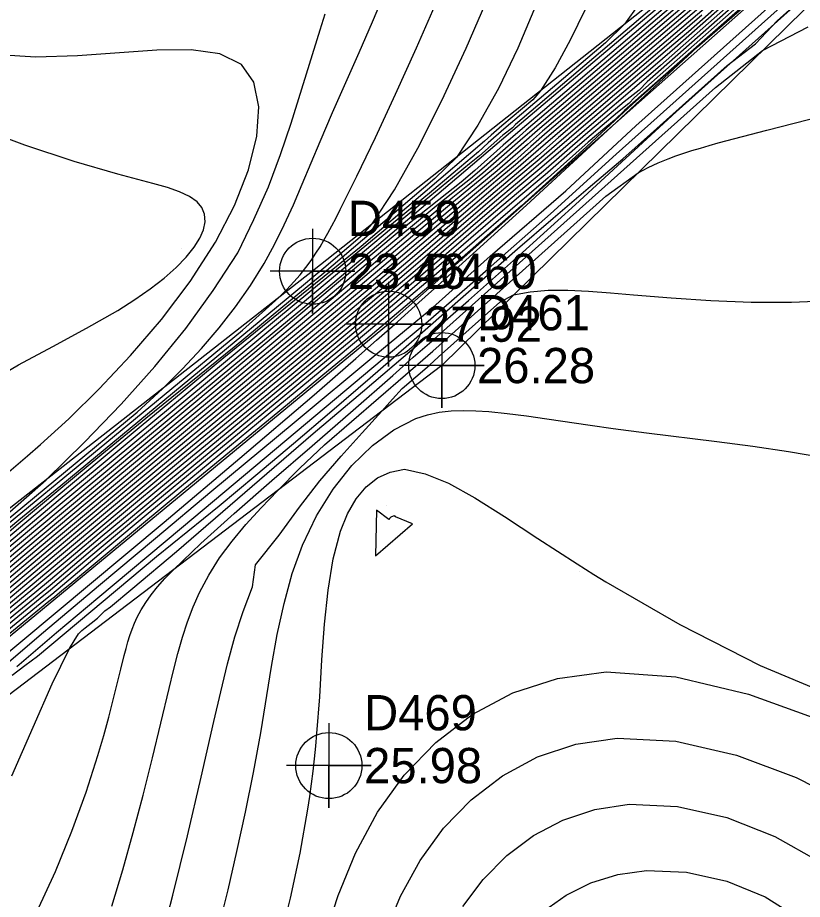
# Model space of a CAD drawing. Extents: x 2356077 to 2359823, y 225951 to 227822.
# Drawn here: x 2356677.4 to 2356733, y 226991.1 to 227053.6 of the extents above; entities that cross this region are included whole.
import ezdxf

# ---------------------------------------------------------------- set-up
doc = ezdxf.new("R2010")
doc.units = 0
for name, color, linetype in [('DTM Contours Major', 7, 'Continuous'), ('DTM Contours Minor', 7, 'Continuous'), ('Exist DTM Breakline', 7, 'Continuous'), ('Exist DTM Breakline Cogo Elevation', 7, 'Continuous'), ('Exist DTM Breakline Cogo Number', 7, 'Continuous'), ('Exist DTM Breakline Cogo Point CELL', 7, 'Continuous'), ('Exist DTM Regular Point CELL', 7, 'Continuous'), ('Exist DTM Regular Point Cogo Elevation', 7, 'Continuous'), ('Exist DTM Regular Point Cogo Number', 7, 'Continuous'), ('PH Exist DTM Point', 7, 'Continuous')]:
    doc.layers.add(name, color=color, linetype=linetype)

msp = doc.modelspace()

# ---------------------------------------------------------------- linework, layer by layer
at = {"layer": 'DTM Contours Major'}
for points in [[(2356736.154, 227061.856), (2356722.941, 227050.189), (2356721.929, 227049.303), (2356717.553, 227045.575), (2356714.539, 227042.973), (2356712.838, 227041.549), (2356711.152, 227040.115), (2356709.481, 227038.677), (2356705.347, 227035.105), (2356702.842, 227032.966), (2356701.073, 227031.472), (2356698.665, 227029.46), (2356696.111, 227027.342), (2356688.206, 227020.82), (2356685.706, 227018.748), (2356683.236, 227016.686), (2356679.71, 227013.717), (2356678.591, 227012.78), (2356668.345, 227004.388)], [(2356729.518, 227059.304), (2356713.432, 227045.6), (2356712.71, 227044.972), (2356710.444, 227042.972), (2356709.478, 227042.157), (2356708.482, 227041.368), (2356707.048, 227040.212), (2356705.641, 227039.058), (2356704.252, 227037.903), (2356701.485, 227035.576), (2356697.397, 227032.135), (2356693.102, 227028.545), (2356682.449, 227019.674), (2356677.954, 227015.918), (2356673.699, 227012.35)], [(2356676.977, 226999.821), (2356678.47, 227003.273), (2356679.827, 227006.346), (2356681.066, 227008.837), (2356681.384, 227009.387), (2356681.697, 227009.884), (2356681.937, 227010.125), (2356682.162, 227010.311), (2356682.601, 227010.639), (2356683.037, 227011.004), (2356683.553, 227011.518), (2356683.972, 227011.787), (2356685.554, 227013.109), (2356688.63, 227015.729), (2356698.316, 227024.09), (2356701.825, 227027.055), (2356705.504, 227030.182), (2356709.348, 227033.532), (2356713.169, 227036.936), (2356716.924, 227040.341), (2356724.062, 227046.907), (2356733.497, 227055.356)], [(2356717.626, 227054.212), (2356716.538, 227051.977), (2356715.472, 227050.028), (2356714.437, 227048.394), (2356713.89, 227047.758), (2356711.712, 227045.903), (2356710.944, 227045.236), (2356710.482, 227044.831), (2356701.737, 227037.351), (2356700.104, 227036.026), (2356697.5, 227033.93), (2356694.726, 227031.676), (2356692.002, 227029.444), (2356689.112, 227027.063), (2356686.137, 227024.598), (2356683.16, 227022.118), (2356680.26, 227019.691), (2356676.405, 227016.442)], [(2356725.678, 227054.264), (2356715.221, 227045.356), (2356713.951, 227044.244), (2356712.67, 227043.137), (2356711.288, 227041.981), (2356709.946, 227040.849), (2356702.897, 227034.856), (2356700.549, 227032.877), (2356698.699, 227031.332), (2356694.781, 227028.083), (2356688.67, 227023.032), (2356685.125, 227020.088), (2356681.648, 227017.188), (2356676.515, 227012.882)], [(2356675.811, 227017.665), (2356679.39, 227020.795), (2356682.125, 227023.486), (2356684.706, 227026.166), (2356687.107, 227028.844), (2356689.296, 227031.527), (2356691.246, 227034.222), (2356692.986, 227036.901), (2356694.13, 227039.264), (2356695.151, 227041.584), (2356696.023, 227043.871), (2356696.777, 227046.099), (2356698.069, 227050.273), (2356698.828, 227052.705), (2356699.18, 227053.861)], [(2356695.921, 226987.929), (2356696.722, 226991.141), (2356697.408, 226994.325), (2356697.96, 226997.437), (2356698.095, 226998.342), (2356698.218, 226999.239), (2356698.329, 227000.131), (2356698.429, 227001.021), (2356698.518, 227001.911), (2356698.598, 227002.805), (2356698.789, 227005.424), (2356698.953, 227008.033), (2356699.136, 227010.57), (2356699.385, 227012.977), (2356699.747, 227015.195), (2356700.267, 227017.165), (2356700.765, 227018.401), (2356701.369, 227019.457), (2356702.075, 227020.311), (2356702.882, 227020.945), (2356703.788, 227021.337), (2356704.813, 227021.559), (2356706.258, 227021.225), (2356707.914, 227020.558), (2356709.781, 227019.531), (2356711.883, 227018.208), (2356714.244, 227016.653), (2356717.036, 227014.836), (2356718.217, 227014.092), (2356719.083, 227013.558), (2356724.321, 227010.533), (2356730.024, 227007.639), (2356735.824, 227005.205)]]:
    msp.add_lwpolyline(points, dxfattribs=at)
at = {"layer": 'DTM Contours Minor'}
for points in [[(2356735.682, 227062.082), (2356724.925, 227052.584), (2356723.457, 227051.312), (2356715.932, 227044.9), (2356714.351, 227043.522), (2356712.766, 227042.187), (2356711.211, 227040.863), (2356705.741, 227036.16), (2356703.843, 227034.54), (2356701.871, 227032.871), (2356700.837, 227032.003), (2356698.663, 227030.189), (2356696.367, 227028.287), (2356689.217, 227022.388), (2356685.422, 227019.244), (2356682.568, 227016.861), (2356678.401, 227013.357), (2356676.583, 227011.851)], [(2356736.273, 227061.639), (2356722.003, 227049.038), (2356721.441, 227048.428), (2356720.364, 227047.616), (2356717.629, 227045.287), (2356714.647, 227042.698), (2356712.876, 227041.213), (2356711.116, 227039.713), (2356707.614, 227036.689), (2356705.116, 227034.535), (2356702.829, 227032.584), (2356701.221, 227031.226), (2356698.685, 227029.107), (2356695.992, 227026.873), (2356687.687, 227020.018), (2356685.085, 227017.858), (2356682.858, 227015.994), (2356679.678, 227013.312), (2356668.259, 227003.96)], [(2356736.926, 227061.558), (2356723.299, 227049.526), (2356720.971, 227047.456), (2356718.773, 227045.416), (2356717.724, 227044.449), (2356715.337, 227042.269), (2356713.064, 227040.221), (2356710.863, 227038.269), (2356708.697, 227036.376), (2356706.523, 227034.506), (2356703.937, 227032.314), (2356702.061, 227030.743), (2356699.019, 227028.219), (2356695.816, 227025.579), (2356689.234, 227020.164), (2356686.007, 227017.496), (2356682.305, 227014.404), (2356681.08, 227013.377), (2356680.515, 227012.926), (2356679.999, 227012.491), (2356679.594, 227012.17), (2356669.406, 227003.826)], [(2356735.905, 227061.957), (2356723.976, 227051.424), (2356722.736, 227050.344), (2356717.494, 227045.878), (2356714.442, 227043.256), (2356712.803, 227041.87), (2356711.186, 227040.487), (2356705.555, 227035.633), (2356703.772, 227034.11), (2356701.919, 227032.542), (2356700.949, 227031.726), (2356698.66, 227029.817), (2356696.237, 227027.81), (2356688.713, 227021.605), (2356686.307, 227019.614), (2356683.607, 227017.364), (2356681.022, 227015.196), (2356678.466, 227013.039), (2356672.629, 227008.254)], [(2356736.24, 227061.288), (2356721.104, 227047.923), (2356720.696, 227047.495), (2356719.891, 227046.86), (2356717.72, 227045.01), (2356716.867, 227044.266), (2356714.772, 227042.427), (2356712.915, 227040.863), (2356711.068, 227039.285), (2356705.506, 227034.491), (2356703.508, 227032.786), (2356701.412, 227031.016), (2356698.739, 227028.785), (2356695.902, 227026.435), (2356690.045, 227021.606), (2356687.181, 227019.238), (2356684.463, 227016.978), (2356681.553, 227014.532), (2356679.702, 227012.967), (2356678.971, 227012.376), (2356667.614, 227003.074)], [(2356730.285, 227060.31), (2356712.992, 227045.579), (2356711.799, 227044.532), (2356709.781, 227042.751), (2356708.827, 227041.918), (2356707.245, 227040.67), (2356705.753, 227039.482), (2356704.292, 227038.293), (2356702.85, 227037.1), (2356699.98, 227034.693), (2356694.914, 227030.44), (2356689.864, 227026.221), (2356680.205, 227018.166), (2356675.141, 227013.92)], [(2356676.984, 227006.958), (2356677.888, 227007.645), (2356678.783, 227008.309), (2356687.231, 227015.376), (2356691.657, 227018.968), (2356694.263, 227021.127), (2356696.933, 227023.376), (2356699.645, 227025.691), (2356702.375, 227028.047), (2356705.1, 227030.419), (2356712.823, 227037.185), (2356715.339, 227039.37), (2356717.825, 227041.499), (2356720.279, 227043.562), (2356722.246, 227045.313), (2356727.684, 227050.179), (2356729.692, 227051.724), (2356731.224, 227053.35), (2356739.12, 227060.427)], [(2356675.568, 227006.894), (2356679.216, 227009.997), (2356683.118, 227013.29), (2356687.14, 227016.666), (2356691.147, 227020.017), (2356696.974, 227024.874), (2356702.772, 227029.686), (2356704.795, 227031.359), (2356706.814, 227033.036), (2356710.868, 227036.664), (2356716.24, 227041.299), (2356721.201, 227045.913), (2356736.298, 227059.426)], [(2356677.311, 227007.563), (2356680.135, 227009.965), (2356683.054, 227012.427), (2356688.992, 227017.403), (2356694.254, 227021.813), (2356701.312, 227027.739), (2356703.819, 227029.837), (2356706.473, 227032.049), (2356710.545, 227035.605), (2356715.159, 227039.677), (2356719.797, 227043.888), (2356736.828, 227059.136)], [(2356733.513, 227058.557), (2356720.407, 227046.985), (2356719.695, 227046.303), (2356719.005, 227045.752), (2356717.832, 227044.752), (2356714.975, 227042.232), (2356707.064, 227035.423), (2356704.506, 227033.238), (2356702.256, 227031.338), (2356698.835, 227028.485), (2356695.832, 227026.002), (2356689.65, 227020.905), (2356686.631, 227018.407), (2356683.766, 227016.018), (2356681.313, 227013.951), (2356679.794, 227012.679), (2356679.229, 227012.229), (2356667.425, 227002.561)], [(2356728.74, 227058.287), (2356713.844, 227045.598), (2356712.999, 227044.862), (2356711.312, 227043.373), (2356710.362, 227042.55), (2356709.284, 227041.683), (2356708.231, 227040.826), (2356706.877, 227039.712), (2356705.542, 227038.6), (2356702.885, 227036.366), (2356700.186, 227034.089), (2356697.282, 227031.654), (2356692.638, 227027.786), (2356684.489, 227021.011), (2356680.122, 227017.369), (2356675.027, 227013.099)], [(2356727.967, 227057.275), (2356714.232, 227045.575), (2356713.27, 227044.737), (2356711.375, 227043.065), (2356709.108, 227041.2), (2356707.998, 227040.28), (2356706.715, 227039.209), (2356704.173, 227037.069), (2356700.28, 227033.784), (2356697.16, 227031.174), (2356686.297, 227022.152), (2356680.077, 227016.967), (2356674.971, 227012.688)], [(2356727.198, 227056.266), (2356714.593, 227045.528), (2356713.521, 227044.594), (2356712.483, 227043.678), (2356711.363, 227042.719), (2356710.137, 227041.706), (2356708.944, 227040.714), (2356706.557, 227038.707), (2356701.65, 227034.557), (2356698.729, 227032.106), (2356695.289, 227029.244), (2356687.877, 227023.102), (2356681.969, 227018.184), (2356678.125, 227014.969), (2356674.917, 227012.277)], [(2356724.255, 227055.88), (2356712.666, 227046.008), (2356712.464, 227045.772), (2356711.776, 227045.241), (2356710.111, 227043.772), (2356709.42, 227043.211), (2356707.799, 227041.884), (2356706.202, 227040.563), (2356704.623, 227039.247), (2356697.844, 227033.564), (2356693.337, 227029.811), (2356682.897, 227021.135), (2356680.255, 227018.932), (2356676.469, 227015.76)], [(2356724.672, 227055.915), (2356721.357, 227053.096), (2356712.788, 227045.836), (2356702.817, 227037.352), (2356699.855, 227034.853), (2356697.594, 227032.962), (2356692.707, 227028.906), (2356685.323, 227022.786), (2356680.24, 227018.556), (2356676.49, 227015.417)], [(2356673.001, 227005.49), (2356682.483, 227013.387), (2356687.76, 227017.801), (2356693.129, 227022.333), (2356698.392, 227026.838), (2356699.877, 227028.125), (2356701.35, 227029.409), (2356702.823, 227030.703), (2356704.311, 227032.019), (2356705.827, 227033.368), (2356707.383, 227034.763), (2356713.451, 227040.276), (2356719.796, 227046.138), (2356725.582, 227051.514), (2356729.92, 227055.291)], [(2356674.641, 227015.625), (2356677.469, 227017.964), (2356680.429, 227020.402), (2356697.65, 227034.638), (2356698.384, 227035.238), (2356699.088, 227035.834), (2356701.822, 227038.173), (2356702.521, 227038.95), (2356704.089, 227041.365), (2356705.747, 227044.317), (2356707.456, 227047.703), (2356709.179, 227051.419), (2356710.876, 227055.366)], [(2356675.672, 227017.189), (2356685.846, 227025.6), (2356687.644, 227027.259), (2356689.067, 227028.682), (2356690.408, 227030.12), (2356691.662, 227031.58), (2356692.825, 227033.067), (2356693.891, 227034.586), (2356694.855, 227036.142), (2356695.596, 227037.5), (2356696.28, 227038.89), (2356696.924, 227040.314), (2356697.549, 227041.771), (2356698.816, 227044.793), (2356699.708, 227046.854), (2356701.593, 227051.117), (2356702.54, 227053.293), (2356703.458, 227055.482)], [(2356726.435, 227055.263), (2356714.923, 227045.456), (2356713.749, 227044.431), (2356712.619, 227043.433), (2356710.038, 227041.279), (2356707.561, 227039.188), (2356702.9, 227035.234), (2356700.459, 227033.177), (2356698.714, 227031.718), (2356695.037, 227028.665), (2356687.382, 227022.328), (2356683.653, 227019.226), (2356679.982, 227016.159), (2356676.51, 227013.246)], [(2356714.166, 227054.564), (2356712.839, 227051.42), (2356711.456, 227048.548), (2356710.007, 227045.962), (2356708.478, 227043.671), (2356706.948, 227042.183), (2356698.951, 227035.342), (2356698.173, 227034.7), (2356696.183, 227033.068), (2356692.721, 227030.206), (2356686.461, 227025.154), (2356683.339, 227022.597), (2356680.295, 227020.076), (2356677.422, 227017.669), (2356674.412, 227015.121)], [(2356726.839, 227054.918), (2356724.928, 227053.272), (2356715.486, 227045.228), (2356714.123, 227044.032), (2356712.698, 227042.822), (2356711.26, 227041.61), (2356708.484, 227039.246), (2356705.03, 227036.294), (2356702.891, 227034.476), (2356700.64, 227032.581), (2356698.684, 227030.948), (2356694.522, 227027.5), (2356688.082, 227022.181), (2356684.74, 227019.404), (2356681.488, 227016.689), (2356676.522, 227012.517)], [(2356676.662, 227017.648), (2356693.314, 227031.415), (2356695.898, 227033.724), (2356696.46, 227034.296), (2356696.959, 227034.835), (2356697.405, 227035.351), (2356697.808, 227035.855), (2356698.179, 227036.358), (2356698.526, 227036.873), (2356698.812, 227037.327), (2356699.092, 227037.801), (2356699.372, 227038.299), (2356699.656, 227038.825), (2356699.947, 227039.383), (2356700.251, 227039.977), (2356701.422, 227042.333), (2356702.743, 227045.085), (2356704.166, 227048.148), (2356705.646, 227051.438), (2356707.136, 227054.87)], [(2356721.411, 227054.531), (2356720.395, 227053.116), (2356719.046, 227051.797), (2356711.847, 227045.664), (2356710.742, 227044.693), (2356710.037, 227044.076), (2356708.253, 227042.55), (2356706.57, 227041.127), (2356704.959, 227039.814), (2356703.328, 227038.473), (2356698.101, 227034.139), (2356685.857, 227023.973), (2356683.026, 227021.615), (2356680.26, 227019.305), (2356676.441, 227016.099)], [(2356725.878, 227053.748), (2356724.188, 227052.288), (2356715.721, 227045.075), (2356714.263, 227043.79), (2356712.73, 227042.505), (2356711.234, 227041.237), (2356708.331, 227038.751), (2356704.917, 227035.826), (2356702.882, 227034.096), (2356700.735, 227032.289), (2356698.672, 227030.567), (2356696.501, 227028.766), (2356687.493, 227021.328), (2356684.358, 227018.722), (2356681.33, 227016.19), (2356678.342, 227013.679), (2356676.543, 227012.176)], [(2356678.747, 226990.168), (2356680.063, 226993.02), (2356681.23, 226995.881), (2356682.237, 226998.656), (2356683.073, 227001.249), (2356683.486, 227002.663), (2356683.846, 227003.982), (2356684.161, 227005.206), (2356684.695, 227007.381), (2356684.934, 227008.334), (2356685.066, 227008.837), (2356685.201, 227009.316), (2356685.342, 227009.774), (2356685.495, 227010.214), (2356685.663, 227010.641), (2356685.851, 227011.057), (2356686.129, 227011.58), (2356686.456, 227012.105), (2356686.841, 227012.642), (2356687.294, 227013.204), (2356687.824, 227013.802), (2356688.44, 227014.447), (2356690.354, 227016.291), (2356692.719, 227018.422), (2356695.398, 227020.76), (2356698.256, 227023.224), (2356701.157, 227025.734), (2356703.965, 227028.208), (2356705.427, 227029.502), (2356706.907, 227030.779), (2356726.852, 227048.637), (2356730.179, 227051.251), (2356733.421, 227052.932)], [(2356676.434, 227021.086), (2356678.075, 227022.494), (2356679.009, 227023.31), (2356681.001, 227025.132), (2356683.163, 227027.248), (2356685.39, 227029.609), (2356687.576, 227032.164), (2356689.617, 227034.863), (2356691.407, 227037.657), (2356692.747, 227040.257), (2356693.738, 227042.793), (2356694.331, 227045.164), (2356694.478, 227047.267), (2356694.131, 227049.002), (2356693.242, 227050.266), (2356691.722, 227051.016), (2356689.682, 227051.301), (2356687.241, 227051.27), (2356681.618, 227050.863), (2356678.67, 227050.787), (2356676.012, 227050.943)], [(2356684.048, 226990.578), (2356684.837, 226993.142), (2356685.579, 226995.785), (2356686.277, 226998.45), (2356686.931, 227001.079), (2356688.119, 227006.001), (2356688.431, 227007.272), (2356688.744, 227008.481), (2356689.07, 227009.634), (2356689.424, 227010.735), (2356689.817, 227011.79), (2356690.264, 227012.804), (2356690.928, 227014.052), (2356691.699, 227015.26), (2356692.574, 227016.446), (2356693.553, 227017.629), (2356694.634, 227018.827), (2356695.814, 227020.058), (2356697.392, 227021.631), (2356699.121, 227023.274), (2356704.882, 227028.247), (2356706.805, 227029.917), (2356719.078, 227040.909), (2356721.359, 227042.582), (2356721.718, 227042.774), (2356722.073, 227042.953), (2356722.426, 227043.12), (2356722.777, 227043.278), (2356723.13, 227043.427), (2356723.485, 227043.568), (2356724.036, 227043.773), (2356724.6, 227043.967), (2356725.18, 227044.153), (2356725.779, 227044.333), (2356726.401, 227044.512), (2356727.049, 227044.691), (2356730.487, 227045.598), (2356734.358, 227046.593)], [(2356675.052, 227027.571), (2356677.442, 227028.952), (2356679.88, 227030.27), (2356682.259, 227031.549), (2356684.469, 227032.817), (2356685.676, 227033.583), (2356686.775, 227034.349), (2356687.755, 227035.11), (2356688.608, 227035.86), (2356689.326, 227036.594), (2356689.899, 227037.307), (2356690.291, 227037.94), (2356690.547, 227038.544), (2356690.662, 227039.112), (2356690.629, 227039.637), (2356690.442, 227040.112), (2356690.095, 227040.53), (2356689.562, 227040.902), (2356688.858, 227041.226), (2356687.991, 227041.524), (2356686.969, 227041.817), (2356684.489, 227042.475), (2356681.386, 227043.377), (2356677.882, 227044.532), (2356674.142, 227045.941)], [(2356687.306, 226987.23), (2356688.387, 226991.347), (2356689.417, 226995.559), (2356690.389, 226999.714), (2356691.292, 227003.661), (2356691.777, 227005.763), (2356692.266, 227007.759), (2356692.785, 227009.658), (2356693.363, 227011.471), (2356694.027, 227013.206), (2356694.243, 227014.769), (2356695.906, 227016.89), (2356697.35, 227018.874), (2356698.811, 227020.727), (2356700.314, 227022.478), (2356701.795, 227024.126), (2356703.188, 227025.668), (2356703.942, 227026.52), (2356704.64, 227027.284), (2356706.564, 227028.944), (2356707.217, 227029.516), (2356711.556, 227033.402), (2356712.54, 227033.914), (2356713.718, 227034.147), (2356714.996, 227034.255), (2356716.371, 227034.261), (2356717.839, 227034.193), (2356719.397, 227034.074), (2356721.041, 227033.931), (2356723.708, 227033.711), (2356726.506, 227033.527), (2356729.37, 227033.41), (2356732.239, 227033.395), (2356735.048, 227033.514)], [(2356691.648, 226989.07), (2356692.293, 226991.717), (2356692.925, 226994.45), (2356693.531, 226997.237), (2356694.096, 227000.049), (2356694.607, 227002.856), (2356695.378, 227007.561), (2356695.785, 227009.837), (2356696.26, 227012.04), (2356696.839, 227014.155), (2356697.563, 227016.168), (2356698.561, 227018.247), (2356699.745, 227020.144), (2356701.078, 227021.82), (2356702.523, 227023.238), (2356704.043, 227024.358), (2356705.601, 227025.144), (2356706.433, 227025.414), (2356707.271, 227025.593), (2356708.12, 227025.692), (2356708.983, 227025.725), (2356709.867, 227025.704), (2356710.777, 227025.644), (2356712.083, 227025.514), (2356713.451, 227025.342), (2356714.883, 227025.139), (2356717.952, 227024.681), (2356719.596, 227024.447), (2356721.956, 227024.139), (2356726.946, 227023.524), (2356729.498, 227023.19), (2356732.035, 227022.818), (2356734.519, 227022.396)], [(2356702.744, 227015.408), (2356705.378, 227017.693), (2356704.156, 227018.179), (2356704.156, 227018.199), (2356704.138, 227018.218), (2356704.104, 227018.233), (2356704.058, 227018.239), (2356704.002, 227018.233), (2356703.94, 227018.213), (2356703.891, 227018.186), (2356703.841, 227018.149), (2356703.792, 227018.104), (2356703.744, 227018.051), (2356703.7, 227017.991), (2356702.821, 227018.661), (2356702.744, 227015.408)], [(2356699.118, 226988.28), (2356700.089, 226991.32), (2356701.329, 226994.335), (2356702.889, 226997.223), (2356704.782, 226999.85), (2356707.022, 227002.185), (2356709.592, 227004.156), (2356712.473, 227005.692), (2356715.648, 227006.722), (2356719.1, 227007.175), (2356724.034, 227006.834), (2356729.181, 227005.607), (2356734.297, 227003.748)], [(2356703.408, 226988.616), (2356704.516, 226991.285), (2356705.901, 226993.815), (2356707.569, 226996.099), (2356709.528, 226998.118), (2356711.758, 226999.82), (2356714.241, 227001.151), (2356716.956, 227002.055), (2356719.885, 227002.481), (2356724.035, 227002.263), (2356728.328, 227001.277), (2356732.567, 226999.689), (2356736.553, 226997.667), (2356740.091, 226995.377), (2356742.981, 226992.987), (2356744.351, 226991.776), (2356745.197, 226990.593)], [(2356708.945, 226990.55), (2356710.377, 226992.469), (2356712.049, 226994.156), (2356713.939, 226995.57), (2356716.03, 226996.674), (2356718.3, 226997.428), (2356720.732, 226997.794), (2356724.147, 226997.646), (2356727.645, 226996.849), (2356731.063, 226995.505), (2356734.236, 226993.714), (2356737, 226991.578), (2356739.576, 226989.257)], [(2356714.655, 226990.214), (2356716.254, 226991.345), (2356718.016, 226992.221), (2356719.921, 226992.815), (2356721.953, 226993.103), (2356724.789, 226992.987), (2356727.652, 226992.343), (2356730.381, 226991.226), (2356732.812, 226989.692)]]:
    msp.add_lwpolyline(points, dxfattribs=at)
at = {"layer": 'Exist DTM Breakline'}
for points in [[(2356732.647, 227097.121), (2356743.457, 227064.303), (2356707.447, 227028.908), (2356663.982, 226995.84), (2356642.282, 226982.572)], [(2356730.086, 227095.133), (2356740.594, 227064.572), (2356703.676, 227031.845), (2356663.207, 226998.49), (2356641.363, 226985.524)], [(2356734.478, 227064.277), (2356698.288, 227035.595), (2356656.152, 227002.595), (2356634.655, 226991.589)]]:
    msp.add_lwpolyline(points, dxfattribs=at)
at = {"layer": 'Exist DTM Breakline Cogo Point CELL'}
for points in [[(2356698.288, 227038.595), (2356698.288, 227032.595), (2356698.288, 227035.595), (2356701.288, 227035.595), (2356695.288, 227035.595)], [(2356703.676, 227034.845), (2356703.676, 227028.845), (2356703.676, 227031.845), (2356706.676, 227031.845), (2356700.676, 227031.845)], [(2356707.447, 227031.908), (2356707.447, 227025.908), (2356707.447, 227028.908), (2356710.447, 227028.908), (2356704.447, 227028.908)]]:
    msp.add_lwpolyline(points, dxfattribs=at)
for centre in [(2356698.288, 227035.595), (2356703.676, 227031.845), (2356707.447, 227028.908)]:
    msp.add_circle(centre, 2.344, dxfattribs=at)
at = {"layer": 'Exist DTM Regular Point CELL'}
msp.add_lwpolyline([(2356699.44, 227003.537), (2356699.44, 226997.537), (2356699.44, 227000.537), (2356702.44, 227000.537), (2356696.44, 227000.537)], dxfattribs=at)
msp.add_circle((2356699.44, 227000.537), 2.344, dxfattribs=at)
at = {"layer": 'PH Exist DTM Point'}
for p, q in [((2356689.023, 227037.234), (2356689.023, 227037.234)), ((2356703.532, 227018.953), (2356703.532, 227018.953)), ((2356717.201, 227014.325), (2356717.201, 227014.325))]:
    msp.add_line(p, q, dxfattribs=at)

# ---------------------------------------------------------------- texts
at = {"layer": 'Exist DTM Breakline Cogo Elevation'}
for s, p in [('23.46', (2356700.788, 227034.345)), ('27.92', (2356706.176, 227030.595)), ('26.28', (2356709.947, 227027.658))]:
    msp.add_text(s, height=2.5, dxfattribs=at).set_placement(p)
at = {"layer": 'Exist DTM Breakline Cogo Number'}
for s, p in [('D459', (2356700.788, 227038.095)), ('D460', (2356706.176, 227034.345)), ('D461', (2356709.947, 227031.408))]:
    msp.add_text(s, height=2.5, dxfattribs=at).set_placement(p)
at = {"layer": 'Exist DTM Regular Point Cogo Elevation'}
msp.add_text('25.98', height=2.5, dxfattribs=at).set_placement((2356701.94, 226999.288))
at = {"layer": 'Exist DTM Regular Point Cogo Number'}
msp.add_text('D469', height=2.5, dxfattribs=at).set_placement((2356701.94, 227003.038))

doc.saveas('drawing.dxf')
